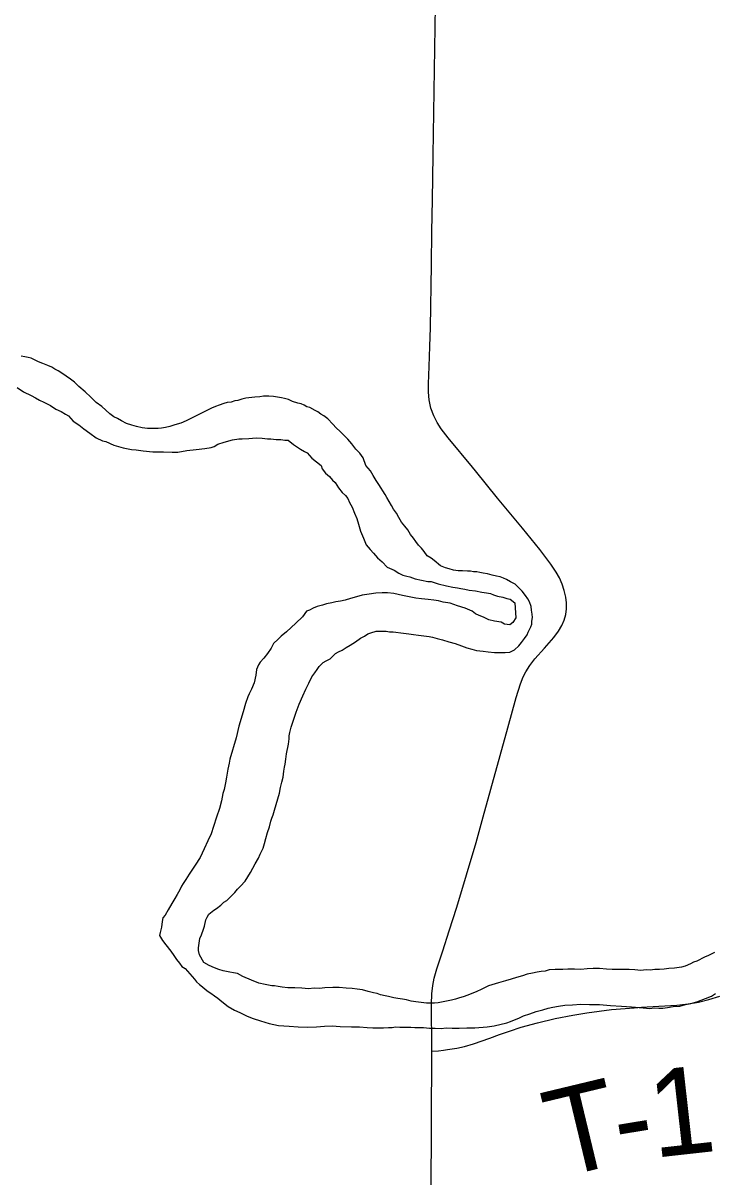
# Model space of a CAD drawing. Extents: x -17 to 88, y -5 to 22.
# Drawn here: x -14.505 to -14.055, y 18.689 to 19.442 of the extents above; entities that cross this region are included whole.
import ezdxf

# ---------------------------------------------------------------- set-up
doc = ezdxf.new("R2010")
doc.units = 0
for name, color, linetype in [('GM_X_Major_River', 7, 'Continuous'), ('GM_X_Township_Road', 7, 'Continuous'), ('GM_X_Township_Road_Text', 7, 'Continuous')]:
    doc.layers.add(name, color=color, linetype=linetype)

msp = doc.modelspace()

# ---------------------------------------------------------------- linework, layer by layer
at = {"layer": 'GM_X_Major_River'}
for points in [[(-14.25549, 19.11347), (-14.25772, 19.11617), (-14.25957, 19.11924), (-14.26104, 19.12193), (-14.26289, 19.12462), (-14.26437, 19.12693), (-14.26584, 19.12961), (-14.26731, 19.1323), (-14.26841, 19.13422), (-14.27247, 19.14075), (-14.27433, 19.14344), (-14.27617, 19.14651), (-14.27801, 19.14958), (-14.28099, 19.15306), (-14.2828, 19.15803), (-14.28502, 19.16111), (-14.28763, 19.16382), (-14.29023, 19.16728), (-14.29283, 19.17037), (-14.29507, 19.17269), (-14.29768, 19.17539), (-14.3003, 19.17772), (-14.30254, 19.18004), (-14.30589, 19.18352), (-14.30852, 19.18547), (-14.3104, 19.18664), (-14.31227, 19.1882), (-14.31415, 19.18899), (-14.31754, 19.19095), (-14.31943, 19.19137), (-14.32131, 19.19254), (-14.3232, 19.19334), (-14.32547, 19.19376), (-14.32887, 19.19496), (-14.33151, 19.19615), (-14.33416, 19.19696), (-14.33605, 19.19737), (-14.3387, 19.1978), (-14.34136, 19.19823), (-14.3444, 19.19829), (-14.34782, 19.19835), (-14.3501, 19.19801), (-14.35353, 19.1977), (-14.35925, 19.19704), (-14.36192, 19.19633), (-14.3646, 19.19563), (-14.3665, 19.19528), (-14.3688, 19.19456), (-14.37146, 19.19424), (-14.37376, 19.19352), (-14.37682, 19.19244), (-14.37911, 19.19172), (-14.3818, 19.19063), (-14.39254, 19.18513), (-14.39561, 19.18367), (-14.3983, 19.1822), (-14.40175, 19.18075), (-14.40557, 19.17968), (-14.40901, 19.1786), (-14.41169, 19.17789), (-14.41436, 19.17756), (-14.41664, 19.17723), (-14.4193, 19.17728), (-14.42349, 19.17735), (-14.4269, 19.1778), (-14.43069, 19.17863), (-14.43371, 19.17944), (-14.43711, 19.18064), (-14.4405, 19.18223), (-14.44313, 19.1838), (-14.44539, 19.18498), (-14.44802, 19.18692), (-14.45064, 19.18925), (-14.45326, 19.19158), (-14.45701, 19.19431), (-14.46036, 19.19779), (-14.4641, 19.20127), (-14.46822, 19.20477), (-14.47121, 19.20748), (-14.47383, 19.20943), (-14.47646, 19.21138), (-14.47946, 19.21333), (-14.48171, 19.21489), (-14.48397, 19.21607), (-14.48585, 19.21725), (-14.48849, 19.21844), (-14.49189, 19.21964), (-14.49453, 19.22083), (-14.49717, 19.22202), (-14.49943, 19.2232), (-14.50132, 19.22361), (-14.50359, 19.22403), (-14.50586, 19.22446)], [(-14.50853, 19.204), (-14.5044, 19.20126), (-14.4995, 19.19889), (-14.49649, 19.19732), (-14.49386, 19.19575), (-14.49122, 19.19456), (-14.48896, 19.19338), (-14.4867, 19.1922), (-14.48332, 19.18986), (-14.47993, 19.18828), (-14.47692, 19.1867), (-14.47504, 19.18553), (-14.47206, 19.18206), (-14.4683, 19.17971), (-14.46493, 19.17699), (-14.46118, 19.17426), (-14.45706, 19.17114), (-14.45291, 19.16917), (-14.45064, 19.16875), (-14.44536, 19.16637), (-14.43931, 19.16474), (-14.43401, 19.1635), (-14.43097, 19.16344), (-14.42642, 19.1626), (-14.41997, 19.1621), (-14.41313, 19.16197), (-14.40743, 19.16187), (-14.40363, 19.16179), (-14.3979, 19.16283), (-14.39181, 19.16347), (-14.38609, 19.16413), (-14.3819, 19.16481), (-14.37998, 19.16553), (-14.37768, 19.16701), (-14.37347, 19.16845), (-14.36812, 19.16987), (-14.36392, 19.17055), (-14.36164, 19.17051), (-14.35745, 19.17081), (-14.35251, 19.1711), (-14.34871, 19.17103), (-14.34529, 19.17058), (-14.34301, 19.17054), (-14.3396, 19.1701), (-14.33656, 19.17004), (-14.33391, 19.16961), (-14.33162, 19.16957), (-14.32825, 19.16685), (-14.32375, 19.16373), (-14.32112, 19.16216), (-14.31923, 19.16136), (-14.31626, 19.15789), (-14.31026, 19.15322), (-14.30954, 19.15093), (-14.30731, 19.14823), (-14.30469, 19.1459), (-14.30284, 19.14359), (-14.30096, 19.14204)], [(-14.30096, 19.14204), (-14.29875, 19.13858), (-14.29652, 19.1355), (-14.29428, 19.13356), (-14.29279, 19.13163), (-14.2917, 19.12895), (-14.28986, 19.12588), (-14.28841, 19.12206), (-14.28695, 19.11861), (-14.28588, 19.1148), (-14.28445, 19.11021), (-14.28263, 19.10562), (-14.28081, 19.10141), (-14.27821, 19.09832), (-14.27597, 19.096), (-14.27336, 19.09292), (-14.27037, 19.09021), (-14.26702, 19.08672), (-14.26249, 19.08474), (-14.25949, 19.08279), (-14.25685, 19.0816), (-14.2542, 19.08079), (-14.25231, 19.08037), (-14.24891, 19.07917), (-14.24474, 19.07833), (-14.24058, 19.0775), (-14.2383, 19.07746), (-14.23376, 19.07585), (-14.22846, 19.07461), (-14.2243, 19.07378), (-14.22126, 19.07334), (-14.21899, 19.07292), (-14.21634, 19.07249), (-14.21369, 19.07168), (-14.20952, 19.07122), (-14.20535, 19.07039), (-14.20232, 19.06995), (-14.19967, 19.06952), (-14.19778, 19.06873), (-14.19513, 19.06792), (-14.19173, 19.0671), (-14.18908, 19.06628), (-14.18681, 19.06586), (-14.18381, 19.06353), (-14.18323, 19.05364), (-14.18519, 19.05064), (-14.18712, 19.04916), (-14.19053, 19.0496), (-14.19279, 19.05079), (-14.19696, 19.05162), (-14.20074, 19.05245), (-14.20414, 19.05404), (-14.20716, 19.05523), (-14.20941, 19.05641), (-14.21167, 19.05797), (-14.21619, 19.05996), (-14.22111, 19.06157), (-14.22602, 19.06318), (-14.23056, 19.06402), (-14.23359, 19.06484), (-14.23662, 19.06527), (-14.24042, 19.06572), (-14.24459, 19.06618), (-14.24838, 19.06663), (-14.25066, 19.06705), (-14.2571, 19.06831), (-14.26278, 19.06956), (-14.26695, 19.07001), (-14.27037, 19.07008), (-14.27456, 19.06978), (-14.27875, 19.06909), (-14.28333, 19.06842), (-14.28715, 19.06735), (-14.29097, 19.06628), (-14.29441, 19.06521), (-14.29747, 19.06451), (-14.30052, 19.06418), (-14.30319, 19.06347), (-14.30662, 19.06278), (-14.3093, 19.06207), (-14.31274, 19.06099), (-14.31542, 19.0599), (-14.31772, 19.05881), (-14.31964, 19.05808), (-14.32237, 19.05434), (-14.32663, 19.05024), (-14.33281, 19.04466), (-14.33629, 19.04168), (-14.33823, 19.03982), (-14.34133, 19.03684), (-14.3429, 19.03383), (-14.34525, 19.03046), (-14.34758, 19.02746), (-14.34991, 19.02485), (-14.35109, 19.02297), (-14.35229, 19.01996), (-14.35274, 19.01617)], [(-14.33062, 18.97892), (-14.3298, 18.98232), (-14.32819, 18.98685), (-14.32657, 18.99214), (-14.32457, 18.99742), (-14.32219, 19.00269), (-14.32021, 19.00721), (-14.31824, 19.01097), (-14.31626, 19.01511), (-14.31431, 19.01773), (-14.31275, 19.01998), (-14.31157, 19.02186), (-14.30886, 19.02446), (-14.30694, 19.02557), (-14.30425, 19.02704), (-14.30077, 19.03039), (-14.29884, 19.03149), (-14.29654, 19.03259), (-14.29385, 19.03444), (-14.29116, 19.03591), (-14.28769, 19.03812), (-14.28461, 19.04034), (-14.28192, 19.04181), (-14.27961, 19.04329), (-14.2777, 19.04401), (-14.27426, 19.04509), (-14.2716, 19.04504), (-14.2697, 19.045), (-14.2678, 19.04497), (-14.26552, 19.04454), (-14.26324, 19.0445), (-14.25642, 19.04362), (-14.253, 19.04317), (-14.24997, 19.04274), (-14.24656, 19.04229), (-14.24314, 19.04185), (-14.23973, 19.04141), (-14.23746, 19.04098), (-14.23443, 19.04017), (-14.23102, 19.03935), (-14.22686, 19.03813), (-14.22271, 19.03691), (-14.21855, 19.03532), (-14.21515, 19.03411), (-14.21175, 19.03329), (-14.20872, 19.03248), (-14.20455, 19.03202), (-14.20113, 19.03157), (-14.19696, 19.03112), (-14.1943, 19.03107), (-14.19202, 19.03103), (-14.19012, 19.03099), (-14.18707, 19.03131), (-14.184, 19.03278), (-14.18129, 19.03538), (-14.17935, 19.03763), (-14.1774, 19.04025), (-14.17584, 19.0425), (-14.17504, 19.04438), (-14.17346, 19.04777), (-14.17266, 19.04965), (-14.17263, 19.05155), (-14.17221, 19.05382), (-14.17254, 19.0561), (-14.17287, 19.05877), (-14.17321, 19.06106), (-14.17429, 19.06411), (-14.1754, 19.06603), (-14.17688, 19.06834), (-14.17911, 19.07104), (-14.18358, 19.07568), (-14.18659, 19.07725), (-14.18923, 19.07882), (-14.19111, 19.07961), (-14.19338, 19.08042), (-14.19565, 19.08084), (-14.19868, 19.08165), (-14.20171, 19.08247), (-14.20436, 19.0829), (-14.20663, 19.08332), (-14.20853, 19.08374), (-14.2108, 19.08378), (-14.2127, 19.08419), (-14.2146, 19.08423), (-14.21802, 19.08429), (-14.22068, 19.08434), (-14.22371, 19.08478), (-14.22674, 19.08559), (-14.22901, 19.0864), (-14.2324, 19.0876), (-14.23652, 19.09109), (-14.23839, 19.09265), (-14.24103, 19.09421), (-14.24288, 19.09691), (-14.24473, 19.09922), (-14.2466, 19.10115), (-14.24846, 19.10347), (-14.24994, 19.10577), (-14.25179, 19.10809), (-14.25364, 19.11116), (-14.25549, 19.11347)], [(-14.35274, 19.01617), (-14.35397, 19.01125), (-14.35557, 19.0071), (-14.35714, 19.0041), (-14.35794, 19.00221), (-14.35954, 18.99769), (-14.36116, 18.9924), (-14.364, 18.98296), (-14.36566, 18.97539), (-14.36972, 18.96142), (-14.37015, 18.95877), (-14.37099, 18.95499), (-14.37184, 18.94969), (-14.37268, 18.94591), (-14.37351, 18.94175), (-14.37432, 18.9391), (-14.37518, 18.93418), (-14.37641, 18.92927), (-14.37842, 18.92361), (-14.38043, 18.91757), (-14.38204, 18.91266), (-14.38403, 18.90814), (-14.38641, 18.90287), (-14.38917, 18.89723), (-14.3923, 18.89235), (-14.39622, 18.88635), (-14.39856, 18.88297), (-14.40013, 18.88034), (-14.40131, 18.87847), (-14.40249, 18.87621), (-14.40407, 18.8732), (-14.40564, 18.87057), (-14.4076, 18.86719), (-14.40996, 18.86306), (-14.41192, 18.85968), (-14.41348, 18.85781), (-14.4139, 18.85554), (-14.41435, 18.85175), (-14.41518, 18.84834), (-14.41559, 18.84645), (-14.41375, 18.843), (-14.41152, 18.8403), (-14.40818, 18.83606), (-14.40633, 18.83337), (-14.40448, 18.83068), (-14.40262, 18.82836), (-14.40114, 18.82606), (-14.39889, 18.82488), (-14.39293, 18.81793), (-14.39145, 18.816), (-14.38958, 18.81445), (-14.3877, 18.8129), (-14.38583, 18.81134), (-14.38396, 18.80979), (-14.38208, 18.80861), (-14.37983, 18.80705), (-14.37758, 18.80549), (-14.37496, 18.80317), (-14.37083, 18.80005), (-14.3667, 18.7977), (-14.3633, 18.79611), (-14.35841, 18.79375), (-14.35463, 18.79216), (-14.34972, 18.79054), (-14.34405, 18.78892), (-14.33799, 18.78767), (-14.33115, 18.78716), (-14.32508, 18.78667), (-14.31938, 18.78656), (-14.31329, 18.78683), (-14.30797, 18.78711), (-14.30302, 18.7874), (-14.2977, 18.78692), (-14.29048, 18.78678), (-14.28516, 18.78669), (-14.28023, 18.78621), (-14.27643, 18.78614), (-14.27301, 18.78608), (-14.26959, 18.78602), (-14.26616, 18.78633), (-14.26388, 18.78629), (-14.26159, 18.78663), (-14.25893, 18.78658), (-14.25551, 18.78651), (-14.25171, 18.78644), (-14.24905, 18.78639), (-14.24639, 18.78635), (-14.24335, 18.78629), (-14.23956, 18.78584), (-14.23576, 18.78577), (-14.23196, 18.7857), (-14.22853, 18.78601), (-14.22473, 18.78594), (-14.22017, 18.78586), (-14.21522, 18.78614), (-14.2099, 18.78605), (-14.2019, 18.78666), (-14.19733, 18.78733), (-14.18892, 18.78945), (-14.18663, 18.79017), (-14.18395, 18.79126)], [(-14.21444, 18.8074), (-14.2175, 18.80631), (-14.2198, 18.8056), (-14.22247, 18.80489), (-14.22515, 18.80418), (-14.23392, 18.80244), (-14.23621, 18.8021), (-14.23849, 18.80215), (-14.24153, 18.8022), (-14.24494, 18.80265), (-14.24836, 18.80309), (-14.25139, 18.80353), (-14.25442, 18.80434), (-14.25707, 18.80477), (-14.2601, 18.80521), (-14.26276, 18.80564), (-14.26616, 18.80646), (-14.26844, 18.80688), (-14.27146, 18.8077), (-14.27373, 18.8085), (-14.276, 18.80892), (-14.27941, 18.80974), (-14.28319, 18.81095), (-14.2866, 18.8114), (-14.29001, 18.81184), (-14.29382, 18.81191), (-14.29837, 18.81238), (-14.30255, 18.81245), (-14.30788, 18.81217), (-14.3113, 18.81186), (-14.31473, 18.81192), (-14.31853, 18.81161), (-14.32271, 18.81207), (-14.32727, 18.81215), (-14.33183, 18.81224), (-14.33562, 18.81269), (-14.33828, 18.81312), (-14.34055, 18.81354), (-14.34245, 18.81357), (-14.34661, 18.81441), (-14.35078, 18.81525), (-14.35569, 18.81724), (-14.36134, 18.81962), (-14.36473, 18.82158), (-14.36738, 18.82201), (-14.36966, 18.82243), (-14.37193, 18.82286), (-14.3742, 18.82328), (-14.37685, 18.82409), (-14.37987, 18.82528), (-14.38326, 18.82687), (-14.38665, 18.82883), (-14.38959, 18.83382), (-14.3903, 18.83649), (-14.39027, 18.83839), (-14.38983, 18.84142), (-14.3894, 18.84445), (-14.38821, 18.8467), (-14.387, 18.85048), (-14.38621, 18.85236), (-14.38537, 18.85652), (-14.38457, 18.85841), (-14.3834, 18.86028), (-14.38031, 18.86289), (-14.37839, 18.86399), (-14.37568, 18.86622), (-14.37375, 18.86808), (-14.37183, 18.86918), (-14.36912, 18.87179), (-14.36641, 18.8744), (-14.36484, 18.87665), (-14.36291, 18.87851), (-14.3598, 18.88187), (-14.35628, 18.8875), (-14.35313, 18.89314), (-14.35116, 18.8969), (-14.34997, 18.89953), (-14.348, 18.9033), (-14.34718, 18.90632), (-14.34636, 18.90972), (-14.34515, 18.9135), (-14.34394, 18.91727), (-14.3431, 18.92105), (-14.34231, 18.92294), (-14.34151, 18.9252), (-14.34069, 18.92822), (-14.33744, 18.93917), (-14.33661, 18.94296), (-14.33579, 18.94636), (-14.33497, 18.94976), (-14.33451, 18.95355), (-14.33408, 18.9562), (-14.33367, 18.95809), (-14.33322, 18.9615), (-14.33278, 18.96491), (-14.33236, 18.96718), (-14.33194, 18.96907), (-14.33152, 18.97134), (-14.33108, 18.97475), (-14.33104, 18.97665), (-14.33062, 18.97892)], [(-14.05348, 18.83516), (-14.05732, 18.83333), (-14.06, 18.83224), (-14.06499, 18.82968), (-14.06729, 18.82896), (-14.06921, 18.82786), (-14.07265, 18.8264), (-14.07495, 18.82569), (-14.07952, 18.82501), (-14.08333, 18.8247), (-14.08638, 18.82438), (-14.08943, 18.82406), (-14.09247, 18.82411), (-14.09551, 18.82379), (-14.09818, 18.82384), (-14.1016, 18.82352), (-14.1054, 18.82398), (-14.1092, 18.82405), (-14.113, 18.82412), (-14.11756, 18.8242), (-14.12022, 18.82425), (-14.12402, 18.82432), (-14.12857, 18.82478), (-14.13276, 18.82486), (-14.13656, 18.82455), (-14.14075, 18.82425), (-14.14493, 18.82433), (-14.14911, 18.82441), (-14.15254, 18.82409), (-14.1552, 18.82414), (-14.15748, 18.82418), (-14.16129, 18.82388), (-14.16396, 18.82317), (-14.16663, 18.82284), (-14.1693, 18.8225), (-14.17235, 18.8218), (-14.17579, 18.82111), (-14.17885, 18.82003), (-14.18267, 18.81896), (-14.18611, 18.81788), (-14.18994, 18.81681), (-14.19452, 18.81538), (-14.20102, 18.8136), (-14.20524, 18.8114), (-14.20908, 18.80957), (-14.21176, 18.80848), (-14.21444, 18.8074)], [(-14.18395, 18.79126), (-14.18127, 18.79235), (-14.1782, 18.79381), (-14.17399, 18.79525), (-14.16978, 18.79669), (-14.16558, 18.79775), (-14.16214, 18.79883), (-14.15908, 18.79953), (-14.15526, 18.80022), (-14.15107, 18.8009), (-14.14612, 18.80119), (-14.14079, 18.80147), (-14.13509, 18.80136), (-14.12863, 18.80124), (-14.12142, 18.80073), (-14.11421, 18.80021), (-14.10775, 18.79972), (-14.10016, 18.79919), (-14.09598, 18.79874), (-14.09256, 18.79905), (-14.0899, 18.799), (-14.08724, 18.79896), (-14.08419, 18.79928), (-14.08037, 18.79997), (-14.07619, 18.80027), (-14.07236, 18.80134), (-14.06893, 18.80203), (-14.06511, 18.8031), (-14.05936, 18.80527), (-14.05553, 18.80672), (-14.05284, 18.80857)]]:
    msp.add_lwpolyline(points, dxfattribs=at)
at = {"layer": 'GM_X_Township_Road'}
for points in [[(-14.23805, 18.77075), (-14.23803, 18.77229), (-14.23815, 18.8015), (-14.23796, 18.80828), (-14.23733, 18.81378), (-14.23634, 18.8186), (-14.2347, 18.82455), (-14.23082, 18.83632), (-14.22656, 18.84931), (-14.22171, 18.86474), (-14.20911, 18.90704), (-14.20438, 18.92379), (-14.1883, 18.9819), (-14.18293, 19.00168), (-14.18014, 19.01053), (-14.17829, 19.01509), (-14.1766, 19.01836), (-14.17402, 19.02255), (-14.17068, 19.02696), (-14.1645, 19.03391), (-14.15825, 19.04088), (-14.15525, 19.04492), (-14.15303, 19.04874), (-14.15154, 19.05223), (-14.15053, 19.05589), (-14.15006, 19.05966), (-14.15009, 19.06346), (-14.15053, 19.06722), (-14.1515, 19.07153), (-14.15289, 19.07571), (-14.15467, 19.07974), (-14.15683, 19.08356), (-14.16031, 19.08875), (-14.16743, 19.09821), (-14.17876, 19.11222), (-14.19502, 19.1318), (-14.20945, 19.14967), (-14.21147, 19.15203), (-14.22737, 19.17111), (-14.23184, 19.17704), (-14.23448, 19.18118), (-14.23675, 19.1855), (-14.23866, 19.19066), (-14.23974, 19.19606), (-14.24011, 19.20097), (-14.24015, 19.20652), (-14.23972, 19.21769), (-14.23927, 19.23074), (-14.23891, 19.24316), (-14.2382, 19.28418), (-14.23797, 19.30593), (-14.2376, 19.32643), (-14.23715, 19.35564), (-14.23551, 19.45313)], [(-14.23805, 18.77075), (-14.23351, 18.77112), (-14.23036, 18.77154), (-14.22778, 18.77184), (-14.22159, 18.77276), (-14.21672, 18.77387), (-14.21075, 18.77566), (-14.20019, 18.77943), (-14.19375, 18.78174), (-14.1873, 18.78396), (-14.17963, 18.78642), (-14.16891, 18.78941), (-14.15748, 18.79213), (-14.14594, 18.79439), (-14.13677, 18.79589), (-14.1288, 18.79706), (-14.1208, 18.79795), (-14.10602, 18.7992), (-14.10109, 18.79955), (-14.08993, 18.80012), (-14.07812, 18.80093), (-14.07068, 18.80177), (-14.06392, 18.80294), (-14.05723, 18.80451), (-14.05005, 18.80668)], [(-14.23835, 18.45341), (-14.23847, 18.45918), (-14.23864, 18.50207), (-14.23891, 18.53498), (-14.23877, 18.56106), (-14.23887, 18.59335), (-14.23875, 18.62131), (-14.23853, 18.64617), (-14.2384, 18.67724), (-14.23805, 18.77075)]]:
    msp.add_lwpolyline(points, dxfattribs=at)

# ---------------------------------------------------------------- texts
at = {"layer": 'GM_X_Township_Road_Text'}
for s, rotation, p in [('T', 13.50615, (-14.15569, 18.68778)), ('1', 6.37755, (-14.09318, 18.70116)), ('-', 9.31089, (-14.11544, 18.69749))]:
    msp.add_text(s, height=0.05682, rotation=rotation, dxfattribs=at).set_placement(p)

doc.saveas('drawing.dxf')
